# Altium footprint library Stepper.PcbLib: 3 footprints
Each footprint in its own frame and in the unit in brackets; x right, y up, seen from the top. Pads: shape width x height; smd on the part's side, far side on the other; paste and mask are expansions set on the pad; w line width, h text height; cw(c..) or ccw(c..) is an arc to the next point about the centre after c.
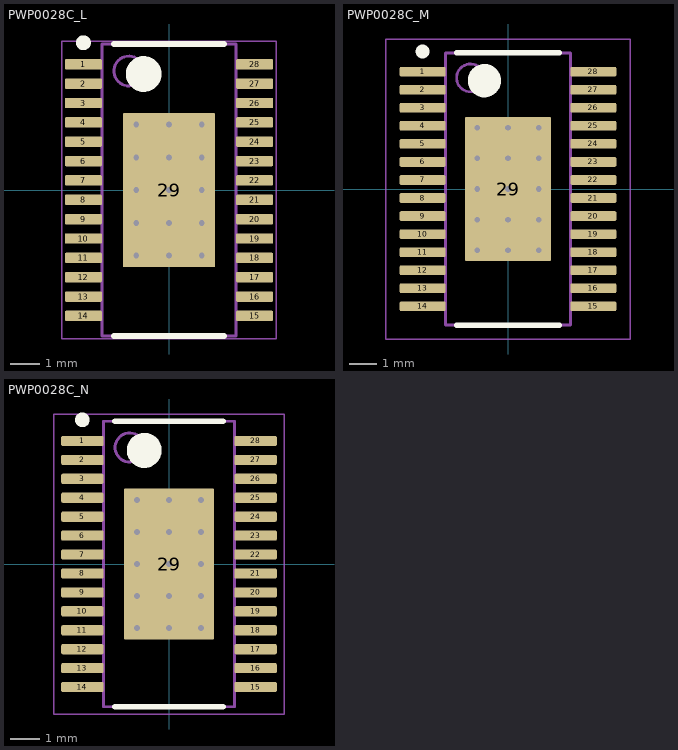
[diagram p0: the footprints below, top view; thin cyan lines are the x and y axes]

## PWP0028C_L [mm] "SOP, 28-Leads, Body 9.8x4.5mm, Pitch 0.65mm, Thermal Pad 5.18x3.1mm, IPC High Density"
height 1.2
pads (29):
  rrect29% 1.25x0.35 smd: 1(-2.875,4.225) 2(-2.875,3.575) 3(-2.875,2.925) 4(-2.875,2.275) 5(-2.875,1.625) 6(-2.875,0.975) 7(-2.875,0.325) 8(-2.875,-0.325) 9(-2.875,-0.975) 10(-2.875,-1.625) 11(-2.875,-2.275) 12(-2.875,-2.925) 13(-2.875,-3.575) 14(-2.875,-4.225) 15(2.875,-4.225) 16(2.875,-3.575) 17(2.875,-2.925) 18(2.875,-2.275) 19(2.875,-1.625) 20(2.875,-0.975) 21(2.875,-0.325) 22(2.875,0.325) 23(2.875,0.975) 24(2.875,1.625) 25(2.875,2.275) 26(2.875,2.925) 27(2.875,3.575) 28(2.875,4.225)
  rrect3% 3.1x5.18 smd: 29(0,0)
via -1.1,2.2 diameter 0.5 hole 0.2
via 0,2.2 diameter 0.5 hole 0.2
via 1.1,2.2 diameter 0.5 hole 0.2
via -1.1,1.1 diameter 0.5 hole 0.2
via 0,1.1 diameter 0.5 hole 0.2
via 1.1,1.1 diameter 0.5 hole 0.2
via -1.1,0 diameter 0.5 hole 0.2
via 0,0 diameter 0.5 hole 0.2
via 1.1,0 diameter 0.5 hole 0.2
via -1.1,-1.1 diameter 0.5 hole 0.2
via 0,-1.1 diameter 0.5 hole 0.2
via 1.1,-1.1 diameter 0.5 hole 0.2
via -1.1,-2.2 diameter 0.5 hole 0.2
via 0,-2.2 diameter 0.5 hole 0.2
via 1.1,-2.2 diameter 0.5 hole 0.2
Top Overlay:
  circle w0.25: c-2.875,4.95 r0.125
  circle w0.6: c-0.85,3.9 r0.3
  lines w0.2: -1.85,-4.9 1.85,-4.9 ; -1.85,4.9 1.85,4.9
Mechanical 1:
  text ".Designator" at -1.524,-0.508 h1.02
Mechanical 13:
  circle w0.1: c-1.35,4 r0.5
  lines w0.1: -2.25,-4.9 -2.25,4.9 2.25,4.9 2.25,-4.9 -2.25,-4.9
Mechanical 15:
  lines w0.05: -3.6,-5 -3.6,5 3.6,5 3.6,-5 -3.6,-5
  lines w0.1: -0.5,0 0.5,0 ; 0,-0.5 0,0.5
3D body: height 1.2, standoff 0.05, extent -2.25,-4.9 2.25,4.9

## PWP0028C_M [mm] "SOP, 28-Leads, Body 9.8x4.5mm, Pitch 0.65mm, Thermal Pad 5.18x3.1mm, IPC Low Density"
height 1.2
pads (29):
  rrect29% 1.65x0.35 smd: 1(-3.075,4.225) 2(-3.075,3.575) 3(-3.075,2.925) 4(-3.075,2.275) 5(-3.075,1.625) 6(-3.075,0.975) 7(-3.075,0.325) 8(-3.075,-0.325) 9(-3.075,-0.975) 10(-3.075,-1.625) 11(-3.075,-2.275) 12(-3.075,-2.925) 13(-3.075,-3.575) 14(-3.075,-4.225) 15(3.075,-4.225) 16(3.075,-3.575) 17(3.075,-2.925) 18(3.075,-2.275) 19(3.075,-1.625) 20(3.075,-0.975) 21(3.075,-0.325) 22(3.075,0.325) 23(3.075,0.975) 24(3.075,1.625) 25(3.075,2.275) 26(3.075,2.925) 27(3.075,3.575) 28(3.075,4.225)
  rrect3% 3.1x5.18 smd: 29(0,0)
via -1.1,2.2 diameter 0.5 hole 0.2
via 0,2.2 diameter 0.5 hole 0.2
via 1.1,2.2 diameter 0.5 hole 0.2
via -1.1,1.1 diameter 0.5 hole 0.2
via 0,1.1 diameter 0.5 hole 0.2
via 1.1,1.1 diameter 0.5 hole 0.2
via -1.1,0 diameter 0.5 hole 0.2
via 0,0 diameter 0.5 hole 0.2
via 1.1,0 diameter 0.5 hole 0.2
via -1.1,-1.1 diameter 0.5 hole 0.2
via 0,-1.1 diameter 0.5 hole 0.2
via 1.1,-1.1 diameter 0.5 hole 0.2
via -1.1,-2.2 diameter 0.5 hole 0.2
via 0,-2.2 diameter 0.5 hole 0.2
via 1.1,-2.2 diameter 0.5 hole 0.2
Top Overlay:
  circle w0.25: c-3.075,4.95 r0.125
  circle w0.6: c-0.85,3.9 r0.3
  lines w0.2: -1.85,-4.9 1.85,-4.9 ; -1.85,4.9 1.85,4.9
Mechanical 1:
  text ".Designator" at -1.524,-0.508 h1.02
Mechanical 13:
  circle w0.1: c-1.35,4 r0.5
  lines w0.1: -2.25,-4.9 -2.25,4.9 2.25,4.9 2.25,-4.9 -2.25,-4.9
Mechanical 15:
  lines w0.05: -4.4,-5.4 -4.4,5.4 4.4,5.4 4.4,-5.4 -4.4,-5.4
  lines w0.1: -0.5,0 0.5,0 ; 0,-0.5 0,0.5
3D body: height 1.2, standoff 0.05, extent -2.25,-4.9 2.25,4.9

## PWP0028C_N [mm] "SOP, 28-Leads, Body 9.8x4.5mm, Pitch 0.65mm, Thermal Pad 5.18x3.1mm, IPC Medium Density"
height 1.2
pads (29):
  rrect29% 1.45x0.35 smd: 1(-2.975,4.225) 2(-2.975,3.575) 3(-2.975,2.925) 4(-2.975,2.275) 5(-2.975,1.625) 6(-2.975,0.975) 7(-2.975,0.325) 8(-2.975,-0.325) 9(-2.975,-0.975) 10(-2.975,-1.625) 11(-2.975,-2.275) 12(-2.975,-2.925) 13(-2.975,-3.575) 14(-2.975,-4.225) 15(2.975,-4.225) 16(2.975,-3.575) 17(2.975,-2.925) 18(2.975,-2.275) 19(2.975,-1.625) 20(2.975,-0.975) 21(2.975,-0.325) 22(2.975,0.325) 23(2.975,0.975) 24(2.975,1.625) 25(2.975,2.275) 26(2.975,2.925) 27(2.975,3.575) 28(2.975,4.225)
  rrect3% 3.1x5.18 smd: 29(0,0)
via -1.1,2.2 diameter 0.5 hole 0.2
via 0,2.2 diameter 0.5 hole 0.2
via 1.1,2.2 diameter 0.5 hole 0.2
via -1.1,1.1 diameter 0.5 hole 0.2
via 0,1.1 diameter 0.5 hole 0.2
via 1.1,1.1 diameter 0.5 hole 0.2
via -1.1,0 diameter 0.5 hole 0.2
via 0,0 diameter 0.5 hole 0.2
via 1.1,0 diameter 0.5 hole 0.2
via -1.1,-1.1 diameter 0.5 hole 0.2
via 0,-1.1 diameter 0.5 hole 0.2
via 1.1,-1.1 diameter 0.5 hole 0.2
via -1.1,-2.2 diameter 0.5 hole 0.2
via 0,-2.2 diameter 0.5 hole 0.2
via 1.1,-2.2 diameter 0.5 hole 0.2
Top Overlay:
  circle w0.25: c-2.975,4.95 r0.125
  circle w0.6: c-0.85,3.9 r0.3
  lines w0.2: -1.85,-4.9 1.85,-4.9 ; -1.85,4.9 1.85,4.9
Mechanical 1:
  text ".Designator" at -1.524,-0.508 h1.02
Mechanical 13:
  circle w0.1: c-1.35,4 r0.5
  lines w0.1: -2.25,-4.9 -2.25,4.9 2.25,4.9 2.25,-4.9 -2.25,-4.9
Mechanical 15:
  lines w0.05: -3.95,-5.15 -3.95,5.15 3.95,5.15 3.95,-5.15 -3.95,-5.15
  lines w0.1: -0.5,0 0.5,0 ; 0,-0.5 0,0.5
3D body: height 1.2, standoff 0.05, extent -2.25,-4.9 2.25,4.9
